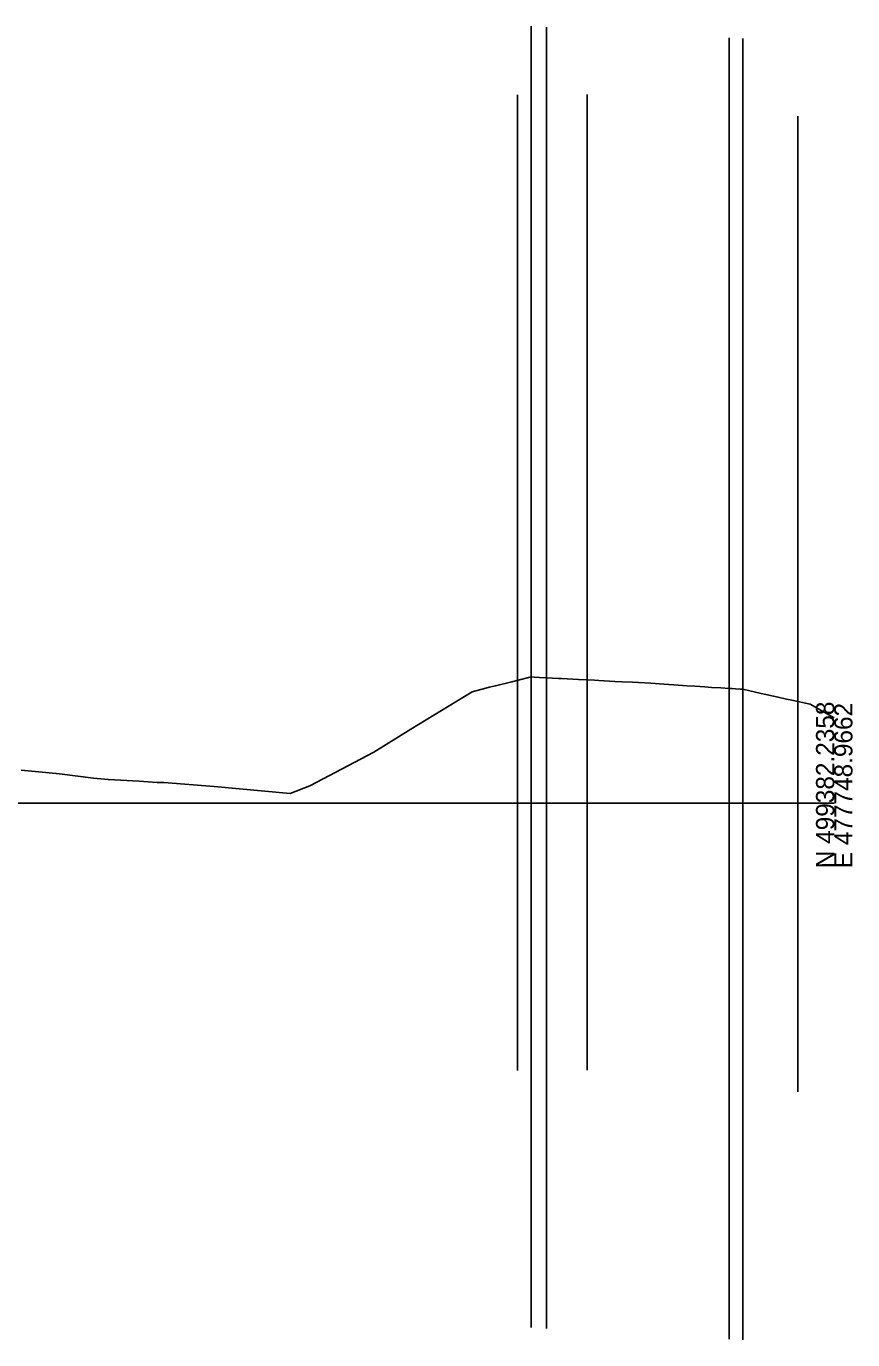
# Model space of a CAD drawing. Extents: x -26 to 403, y -99 to 4540.
# Drawn here: x 275.9 to 402.8, y 1417.5 to 1619.4 of the extents above; entities that cross this region are included whole.
import ezdxf

# ---------------------------------------------------------------- set-up
doc = ezdxf.new("R2010")
doc.units = 0
for name, color, linetype in [('Exist Cross Section Cell', 7, 'Continuous'), ('Exist XS Ground Line', 7, 'Continuous'), ('Scratch_Level_1', 7, 'Continuous'), ('Scratch_Level_2', 7, 'Continuous'), ('Scratch_Level_5', 7, 'Continuous'), ('Scratch_Level_6', 7, 'Continuous')]:
    doc.layers.add(name, color=color, linetype=linetype)

msp = doc.modelspace()

# ---------------------------------------------------------------- linework, layer by layer
at = {"layer": 'Exist Cross Section Cell'}
msp.add_line((200, 1500), (400, 1500), dxfattribs=at)
at = {"layer": 'Exist XS Ground Line'}
msp.add_lwpolyline([(275.1, 1505.05), (280.97, 1504.51), (286.19, 1503.83), (288.47, 1503.63), (293.22, 1503.35), (295.97, 1503.19), (296.99, 1503.15), (304.72, 1502.58), (316.42, 1501.46), (319.42, 1502.66), (329.28, 1507.83), (334.93, 1511.37), (344.36, 1517.12), (346.49, 1517.67), (347, 1517.8), (347.95, 1518.04), (350.46, 1518.66), (353.45, 1519.41), (353.88, 1519.38), (354.72, 1519.33), (355.79, 1519.27), (357.64, 1519.16), (358.11, 1519.14), (360.73, 1519), (363.19, 1518.88), (363.86, 1518.84), (366.28, 1518.71), (367.37, 1518.66), (369.03, 1518.58), (369.95, 1518.54), (371.8, 1518.42), (373.82, 1518.28), (374.57, 1518.23), (375.36, 1518.18), (377.36, 1518.05), (378.59, 1517.97), (380.12, 1517.86), (381.17, 1517.79), (382.58, 1517.71), (383.85, 1517.63), (384.32, 1517.6), (384.82, 1517.57), (385.54, 1517.53), (385.95, 1517.52), (388.78, 1516.87), (391.37, 1516.28), (392.69, 1515.98), (393.48, 1515.81), (396.31, 1515.19), (400, 1513.11)], dxfattribs=at)
at = {"layer": 'Scratch_Level_1'}
for p, q in [((353.45, 1619.41), (353.45, 1419.41)), ((355.79, 1619.27), (355.79, 1419.27)), ((383.85, 1617.63), (383.85, 1417.63)), ((385.95, 1617.52), (385.95, 1417.52))]:
    msp.add_line(p, q, dxfattribs=at)
at = {"layer": 'Scratch_Level_2'}
msp.add_line((351.34, 1568.88), (351.34, 1468.88), dxfattribs=at)
at = {"layer": 'Scratch_Level_5'}
msp.add_line((351.34, 1608.88), (351.34, 1458.88), dxfattribs=at)
at = {"layer": 'Scratch_Level_6'}
for p, q in [((351.34, 1608.88), (351.34, 1458.88)), ((362.06, 1608.93), (362.06, 1458.93)), ((394.4, 1605.61), (394.4, 1455.61))]:
    msp.add_line(p, q, dxfattribs=at)

# ---------------------------------------------------------------- texts
at = {"layer": 'Exist Cross Section Cell'}
for s, p in [('N 499382.2358', (400, 1490)), ('E 477748.9662', (402.8, 1490))]:
    msp.add_text(s, height=2.8, rotation=90, dxfattribs=at).set_placement(p)

doc.saveas('drawing.dxf')
